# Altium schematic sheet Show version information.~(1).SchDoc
size A4; Date: 2025/12/2; DrawnBy: 付浩为; Revision: V1.00; SheetNumber: 1; SheetTotal: 2; Model: GS_4CH_Motherboard; Size: A4; Department: R&D
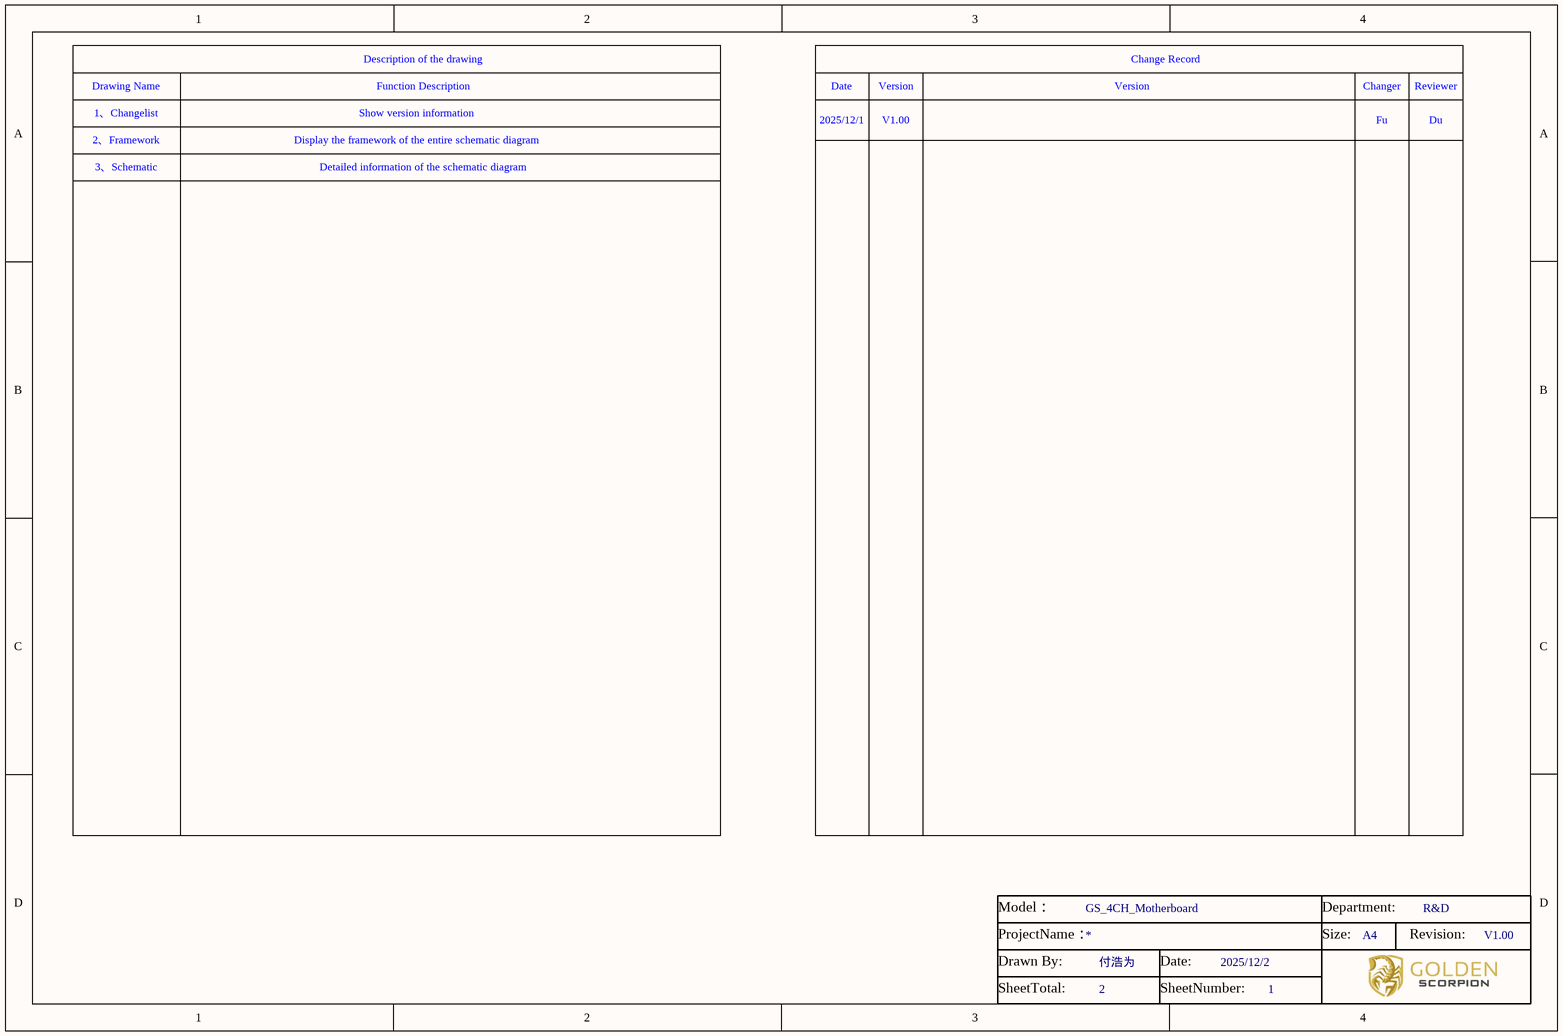
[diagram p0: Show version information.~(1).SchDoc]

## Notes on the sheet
- Drawing Name
- 1、Changelist
- Show version information
- Description of the drawing
- Function Description
- Date
- 2025/12/1
- Version
- V1.00
- Change Record
- Changer
- Fu
- Reviewer
- Du
- 2、Framework
- 3、Schematic
- Display the framework of the entire schematic diagram
- Detailed information of the schematic diagram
